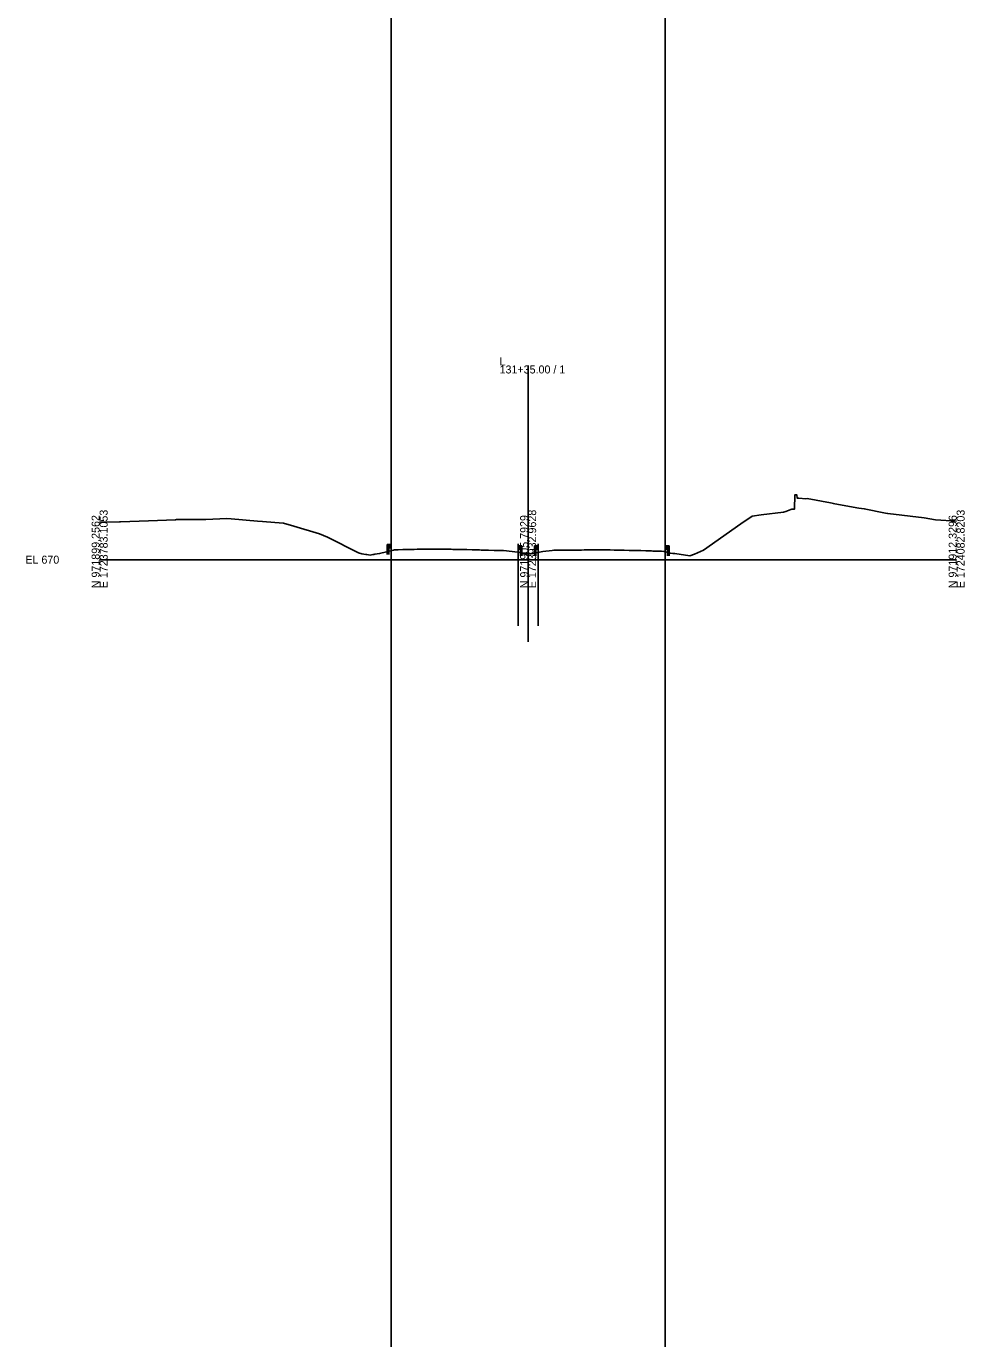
# Model space of a CAD drawing. Extents: x -26 to 303, y -29 to 15026.
# Drawn here: x -25.7 to 302.8, y 2727.3 to 3186.7 of the extents above; entities that cross this region are included whole.
import ezdxf

# ---------------------------------------------------------------- set-up
doc = ezdxf.new("R2010")
doc.units = 0
for name, color, linetype in [('Exist Cross Section Cell', 7, 'Continuous'), ('Exist XS Center Line Elevation Label', 7, 'Continuous'), ('Exist XS Ground Line', 7, 'Continuous'), ('Scratch_Level_0', 7, 'Continuous'), ('Typical Guardrail CELL', 7, 'Continuous')]:
    doc.layers.add(name, color=color, linetype=linetype)

msp = doc.modelspace()

# ---------------------------------------------------------------- linework, layer by layer
at = {"layer": 'Exist Cross Section Cell'}
for p, q in [((150, 3000), (150, 3067.97)), ((0, 3000), (150, 3000)), ((150, 3000), (300, 3000))]:
    msp.add_line(p, q, dxfattribs=at)
at = {"layer": 'Exist XS Ground Line'}
msp.add_lwpolyline([(0, 3013.08), (6.91, 3013.29), (7.34, 3013.3), (17.09, 3013.56), (26.52, 3013.99), (26.93, 3014.01), (36.11, 3014.07), (37.14, 3014.11), (44.5, 3014.4), (46.07, 3014.34), (55.29, 3013.52), (56.96, 3013.34), (61.35, 3012.98), (64.39, 3012.72), (68.01, 3011.7), (76.98, 3009), (79.71, 3007.85), (90.62, 3002.4), (91.83, 3001.99), (93.13, 3001.81), (93.49, 3001.77), (94.69, 3001.59), (95.6, 3001.77), (95.99, 3001.87), (96.35, 3001.94), (97.99, 3002.12), (102.81, 3003.33), (103.16, 3003.41), (103.82, 3003.43), (104.46, 3003.46), (106.08, 3003.53), (107.76, 3003.58), (108.59, 3003.6), (110.11, 3003.62), (111.17, 3003.63), (112.01, 3003.63), (113.62, 3003.63), (114.99, 3003.64), (116.11, 3003.64), (117.39, 3003.65), (118.61, 3003.65), (119.93, 3003.64), (121.1, 3003.63), (122.18, 3003.63), (123.05, 3003.63), (123.59, 3003.62), (124.55, 3003.6), (126.09, 3003.56), (127.76, 3003.52), (128.58, 3003.51), (130.37, 3003.47), (131.09, 3003.45), (133.03, 3003.4), (133.61, 3003.38), (134.24, 3003.37), (135.76, 3003.33), (136.07, 3003.31), (138.11, 3003.27), (138.62, 3003.26), (140.85, 3003.21), (141.34, 3003.19), (146.34, 3002.64), (149.36, 3002.08), (150.19, 3002.07), (151.01, 3002.1), (155.14, 3002.84), (158.41, 3003.25), (158.95, 3003.28), (159.52, 3003.28), (161.14, 3003.3), (162.94, 3003.32), (163.91, 3003.33), (164.5, 3003.35), (165.47, 3003.35), (166.14, 3003.36), (167.74, 3003.37), (168.66, 3003.38), (169.67, 3003.39), (171.16, 3003.4), (172.54, 3003.41), (173.67, 3003.42), (174.91, 3003.42), (176.17, 3003.42), (176.93, 3003.42), (177.29, 3003.41), (177.68, 3003.41), (178.67, 3003.39), (180.11, 3003.35), (181.15, 3003.33), (182.1, 3003.31), (183.64, 3003.28), (185.34, 3003.24), (186.15, 3003.22), (186.89, 3003.21), (188.65, 3003.17), (189.48, 3003.16), (191.15, 3003.09), (193.19, 3003.04), (193.67, 3003.02), (195.87, 3002.95), (196.2, 3002.93), (196.65, 3002.93), (197.51, 3002.91), (197.89, 3002.9), (198.09, 3002.71), (198.92, 3002.5), (199.71, 3002.26), (200.63, 3002.11), (201.33, 3002.11), (206.62, 3001.36), (208.18, 3001.92), (211.41, 3003.36), (224.5, 3012.53), (228.45, 3015.26), (231.61, 3015.65), (239.36, 3016.63), (240.17, 3016.89), (241.92, 3017.54), (241.97, 3017.55), (242.3, 3017.66), (243.22, 3017.66), (243.32, 3022.64), (244.07, 3022.66), (244.17, 3021.57), (244.67, 3021.5), (244.77, 3021.57), (247.21, 3021.3), (247.68, 3021.37), (255.9, 3019.89), (256.48, 3019.74), (256.84, 3019.65), (257.33, 3019.56), (265.8, 3018.03), (267.64, 3017.83), (275.09, 3016.33), (275.91, 3016.15), (288.62, 3014.65), (292.62, 3013.99), (300, 3013.46)], dxfattribs=at)
at = {"layer": 'Scratch_Level_0'}
for p, q in [((102, 15009.56), (102, -28.7)), ((198, 15009.56), (198, -28.7)), ((146.46, 3005.5), (146.46, 2976.8)), ((153.54, 3005.5), (153.54, 2976.8)), ((150, 3000), (150, 2971.3))]:
    msp.add_line(p, q, dxfattribs=at)
at = {"layer": 'Typical Guardrail CELL'}
for p, q in [((101.18, 3005.28), (100.68, 3005.28)), ((100.68, 3005.28), (100.68, 3002.8)), ((101.18, 3005.28), (101.18, 3002.8)), ((101.18, 3005.28), (101.68, 3005.28)), ((101.18, 3004.12), (101.68, 3004.12)), ((101.68, 3005.28), (101.68, 3004.12)), ((101.68, 3005.28), (101.97, 3005.08)), ((101.68, 3004.75), (101.97, 3004.95)), ((101.68, 3004.7), (101.68, 3004.75)), ((101.68, 3004.7), (101.68, 3004.66)), ((101.68, 3004.66), (101.97, 3004.45)), ((101.68, 3004.12), (101.97, 3004.33)), ((146.78, 3004.86), (146.49, 3004.66)), ((146.78, 3004.33), (146.49, 3004.53)), ((146.78, 3004.23), (146.49, 3004.03)), ((147.28, 3004.86), (146.78, 3004.86)), ((146.78, 3004.86), (146.78, 3003.7)), ((146.78, 3004.28), (146.78, 3004.33)), ((146.78, 3004.28), (146.78, 3004.23)), ((147.28, 3004.86), (147.28, 3002.37)), ((147.28, 3004.86), (147.78, 3004.86)), ((147.78, 3004.86), (147.78, 3002.37)), ((152.72, 3004.81), (152.22, 3004.81)), ((152.22, 3004.81), (152.22, 3002.32)), ((152.72, 3004.81), (152.72, 3002.32)), ((152.72, 3004.81), (153.22, 3004.81)), ((153.22, 3004.81), (153.22, 3003.65)), ((153.22, 3004.81), (153.51, 3004.6)), ((153.22, 3004.27), (153.51, 3004.48)), ((153.22, 3004.23), (153.22, 3004.27)), ((153.22, 3004.23), (153.22, 3004.18)), ((153.22, 3004.18), (153.51, 3003.98)), ((198.32, 3004.86), (198.03, 3004.66)), ((198.32, 3004.33), (198.03, 3004.53)), ((198.32, 3004.23), (198.03, 3004.03)), ((198.82, 3004.86), (198.32, 3004.86)), ((198.32, 3004.86), (198.32, 3003.7)), ((198.32, 3004.28), (198.32, 3004.33)), ((198.32, 3004.28), (198.32, 3004.23)), ((198.82, 3004.86), (198.82, 3002.37)), ((198.82, 3004.86), (199.32, 3004.86)), ((199.32, 3004.86), (199.32, 3002.37)), ((101.18, 3002.8), (100.68, 3002.8)), ((100.68, 3002.8), (100.68, 3001.79)), ((101.18, 3002.8), (101.18, 3001.79)), ((146.78, 3003.7), (146.49, 3003.9)), ((147.28, 3003.7), (146.78, 3003.7)), ((147.28, 3002.37), (147.78, 3002.37)), ((147.28, 3002.37), (147.28, 3001.37)), ((147.78, 3002.37), (147.78, 3001.37)), ((152.72, 3002.32), (152.22, 3002.32)), ((152.22, 3002.32), (152.22, 3001.31)), ((152.72, 3003.65), (153.22, 3003.65)), ((152.72, 3002.32), (152.72, 3001.31)), ((153.22, 3003.65), (153.51, 3003.85)), ((198.32, 3003.7), (198.03, 3003.9)), ((198.82, 3003.7), (198.32, 3003.7)), ((198.82, 3002.37), (199.32, 3002.37)), ((198.82, 3002.37), (198.82, 3001.37)), ((199.32, 3002.37), (199.32, 3001.37))]:
    msp.add_line(p, q, dxfattribs=at)
for centre, start, end in [((101.92, 3005.02), 304.9888, 54.997), ((101.92, 3004.39), 304.9634, 54.9941), ((146.54, 3004.59), 125.003, 235.0112), ((153.46, 3004.54), 304.9888, 54.997), ((198.08, 3004.59), 125.003, 235.0112), ((146.54, 3003.97), 125.0059, 235.0366), ((153.46, 3003.91), 304.9634, 54.9941), ((198.08, 3003.97), 125.0059, 235.0366)]:
    msp.add_arc(centre, 0.0776, start, end, dxfattribs=at)

# ---------------------------------------------------------------- texts
at = {"layer": 'Exist Cross Section Cell'}
for s, p in [('L', (140, 3067.97)), ('131+35.00 / 1', (140, 3065.17)), ('EL 670', (-26, 2998.6))]:
    msp.add_text(s, height=2.8, dxfattribs=at).set_placement(p)
for s, p in [('N 971899.2562', (0, 2990)), ('E 1723783.1053', (2.8, 2990)), ('N 971905.7929', (150, 2990)), ('E 1723932.9628', (152.8, 2990)), ('N 971912.3296', (300, 2990)), ('E 1724082.8203', (302.8, 2990))]:
    msp.add_text(s, height=2.8, rotation=90, dxfattribs=at).set_placement(p)
at = {"layer": 'Exist XS Center Line Elevation Label'}
msp.add_text('672.07', height=0.18, dxfattribs=at).set_placement((149.61, 3001.58))

doc.saveas('drawing.dxf')
